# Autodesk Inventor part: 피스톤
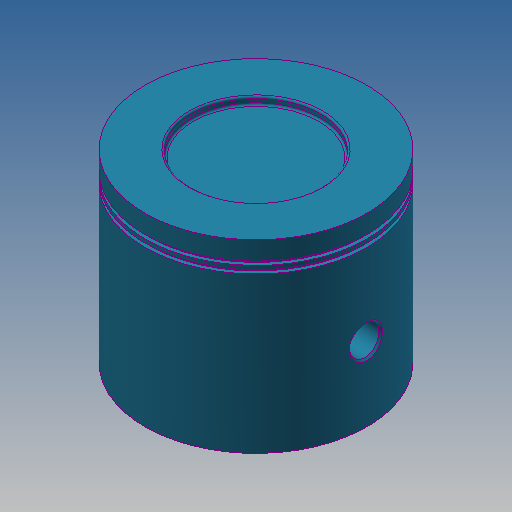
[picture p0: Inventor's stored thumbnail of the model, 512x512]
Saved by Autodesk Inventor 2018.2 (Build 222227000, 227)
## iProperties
Created: 2016-11
Part Number: 피스톤
Material: 강철, 탄소
Document SubType Name: Modeling
Designer: mduedu
Density: 7.87 g/cm^3
Mass: 410.115 g
Surface Area: 237.491 cm^2
Volume: 52.1112 cm^3
Appearance: 터키옥색
Author: mduedu
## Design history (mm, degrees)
sketch "스케치1"
  geometry: C1 r 30 at (0, 0); 1 further point
  constraints: 1 centre point, 1 coincident
  dimensions: "d0" = 60 diameter of C1
extrude "돌출1" new body sketch "스케치1" distance "d1" = 50; taper "d2" = 0 deg
sketch "스케치2"
  geometry: C1 r 28 at (0, 0); 1 further point
  constraints: 1 centre point, 1 coincident
  dimensions: "d3" = 56 diameter of C1
extrude "돌출2" cut sketch "스케치2" distance "d4" = 45; taper "d5" = 0 deg
sketch "스케치3"
  geometry: L1 (30, 0)-(30, 50) reference; L2 (30, 45)-(29, 45); L3 (29, 45)-(29, 44); L4 (29, 44)-(30, 44); L5 (30, 44)-(30, 45); L6 (30, 43)-(29, 43); L7 (29, 43)-(29, 42); L8 (29, 42)-(30, 42); L9 (30, 42)-(30, 43); L10 (30, 50)-(-30, 50) reference; L11 (0, 50)-(0, 0)
  constraints: 18 end point, 4 parallel, 3 equal length, 3 perpendicular, 2 horizontal, 2 point on line, 1 midpoint
  dimensions: "d6" = 1 distance of L2.start L2.end; "d8" = 5 distance between parallel lines of L10 L2; "d9" = 1 distance between parallel lines of L6 L4
revolve "회전1" sketch "스케치3" stored, may be unused: angle "d10" = 90 deg
node "작업 평면1"
sketch "스케치4"
  geometry: L1 (0, -22.978)-(45, -22.978) reference; L2 (45, -22.978)-(45, 22.978) reference; L3 (45, 22.978)-(0, 22.978) reference; L4 (0, 22.978)-(0, 25.377) reference; L5 (0, 25.377)-(42, 25.377) reference; L6 (42, 25.377)-(42, 24.187) reference; L7 (42, 24.187)-(43, 24.187) reference; L8 (43, 24.187)-(43, 25.377) reference; L9 (43, 25.377)-(44, 25.377) reference; L10 (44, 25.377)-(44, 24.187) reference; L11 (44, 24.187)-(45, 24.187) reference; L12 (45, 24.187)-(45, 25.377) reference; L13 (45, 25.377)-(50, 25.377) reference; L14 (50, 25.377)-(50, -25.377) reference; L15 (50, -25.377)-(45, -25.377) reference; L16 (45, -25.377)-(45, -24.187) reference; L17 (45, -24.187)-(44, -24.187) reference; L18 (44, -24.187)-(44, -25.377) reference; L19 (44, -25.377)-(43, -25.377) reference; L20 (43, -25.377)-(43, -24.187) reference; L21 (43, -24.187)-(42, -24.187) reference; L22 (42, -24.187)-(42, -25.377) reference; L23 (42, -25.377)-(0, -25.377) reference; L24 (0, -25.377)-(0, -22.978) reference; L25 (12.5, 22.978)-(45, 22.978); L26 (45, 22.978)-(45, -22.978); L27 (45, -22.978)-(12.5, -22.978); L28 (12.5, -22.978)-(12.5, 22.978); C1 r 7.5 at (20, 0); C2 r 4 at (20, 0); 1 further point
  constraints: 8 end point, 2 centre point, 2 parallel, 1 coincident, 1 horizontal, 1 horizontal alignment, 1 perpendicular, 1 point on line, 1 tangent
  dimensions: "d12" = 15 diameter of C1; "d13" = 8 diameter of C2; "d14" = 20 distance of point (0, 0) C1.centre
  node "절단 모서리 투영1"
extrude "돌출3" join sketch "스케치4" stored distance "d15" = 11.75; taper "d16" = 0 deg
extrude "돌출4" cut sketch "스케치4" extent not by distance; stored distance "d17" = 72; taper "d18" = 0 deg
fillet "모깎기2" dims "d20" = 3
chamfer "모따기1" distance "d21" = 0.5; stored, may be unused: second distance "d22" = 2, angle "d23" = 45 deg
chamfer "모따기2" distance "d24" = 0.5; stored, may be unused: second distance "d25" = 2, angle "d26" = 45 deg
sketch "스케치5"
  geometry: C1 r 17.5 at (0, 0); 1 further point
  constraints: 1 centre point, 1 coincident
  dimensions: "d27" = 35 diameter of C1
extrude "돌출5" cut sketch "스케치5" distance "d28" = 2; taper "d29" = 0 deg
fillet "모깎기3" dims "d30" = 0.5
node "솔리드1"
mirror "대칭1"
other parameters: "d11" = -16
